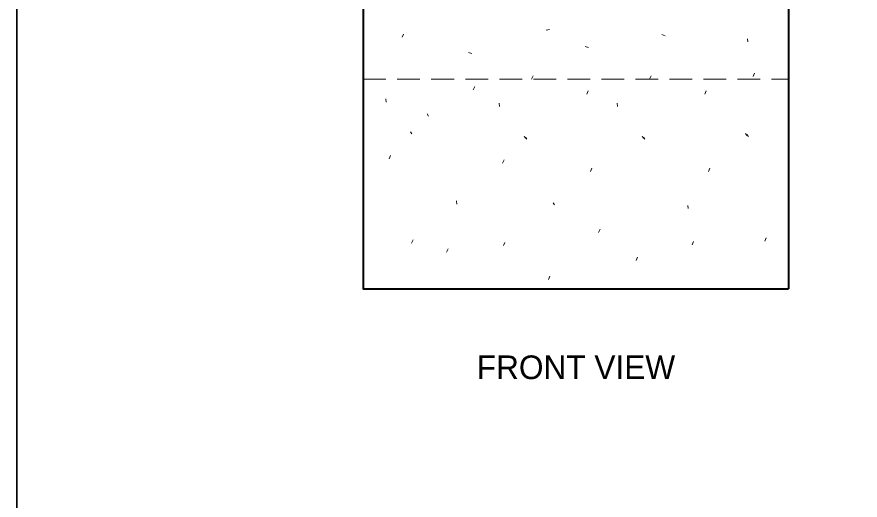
# Model space of a CAD drawing. Extents: x 99860 to 103153, y 99998 to 102077.
# Drawn here: x 99862 to 100576, y 101138 to 101547 of the extents above; entities that cross this region are included whole.
import ezdxf
from ezdxf.enums import TextEntityAlignment as Align

# ---------------------------------------------------------------- set-up
doc = ezdxf.new("R2010")
doc.units = 0
doc.header["$LTSCALE"] = 6.4
doc.linetypes.add('MEDIUM_DASHED', pattern=[4.5, 3, -1.5])
for name, color, linetype, lineweight in [('1', 7, 'Continuous', 13), ('20', 7, 'Continuous', 13), ('7', 7, 'Continuous', 13)]:
    doc.layers.add(name, color=color, linetype=linetype, lineweight=lineweight)

msp = doc.modelspace()

# ---------------------------------------------------------------- linework, layer by layer
at = {"layer": '1', "lineweight": 35}
msp.add_lwpolyline([(99862, 99999.5), (103151, 99999.5), (103151, 102075.5), (99862, 102075.5)], close=True, dxfattribs=at)
at = {"layer": '7', "lineweight": 40}
msp.add_line((100515.171, 101556.572), (100515.171, 101316.572), dxfattribs=at)
at = {"layer": '7'}
for p, q in [((100312.661, 101536.054), (100309.942, 101535.425)), ((100188.029, 101529.482), (100189.279, 101532.252)), ((100407.735, 101531.7), (100410.61, 101530.757)), ((100480.396, 101528.277), (100480.746, 101525.517)), ((100342.974, 101521.73), (100345.86, 101520.778)), ((100244.288, 101516.744), (100247.163, 101515.801)), ((100485.041, 101496.352), (100486.291, 101499.122)), ((100297.621, 101494.062), (100298.861, 101496.832)), ((100397.451, 101494.062), (100398.701, 101496.832)), ((100248.291, 101485.142), (100249.541, 101487.912)), ((100174.201, 101477.462), (100174.541, 101474.692)), ((100344.321, 101481.412), (100345.561, 101484.172)), ((100444.151, 101481.412), (100445.401, 101484.172)), ((100270.221, 101473.732), (100270.571, 101470.962)), ((100370.061, 101473.732), (100370.401, 101470.962)), ((100209.15, 101464.689), (100210.4, 101462.889)), ((100195.231, 101449.512), (100196.401, 101447.712)), ((100291.251, 101445.782), (100292.431, 101443.982)), ((100292.431, 101445.082), (100293.671, 101443.282)), ((100391.091, 101445.782), (100392.261, 101443.982)), ((100392.261, 101445.082), (100393.511, 101443.282)), ((100478.681, 101448.062), (100479.851, 101446.262)), ((100479.851, 101447.372), (100481.101, 101445.572)), ((100177.031, 101426.752), (100178.281, 101429.522)), ((100273.061, 101423.022), (100274.301, 101425.782)), ((100347.431, 101415.962), (100348.671, 101418.722)), ((100447.261, 101415.962), (100448.511, 101418.722)), ((100233.971, 101391.052), (100234.321, 101388.282)), ((100315.756, 101389.57), (100316.926, 101387.77)), ((100429.831, 101387.322), (100430.181, 101384.552)), ((100354.351, 101364.412), (100355.591, 101367.182)), ((100196.121, 101355.422), (100197.371, 101358.192)), ((100273.751, 101353.212), (100274.991, 101355.982)), ((100433.501, 101353.972), (100434.741, 101356.732)), ((100494.931, 101356.942), (100496.181, 101359.712)), ((100225.705, 101347.646), (100226.945, 101350.406)), ((100386.093, 101340.629), (100387.333, 101343.389)), ((100311.913, 101324.591), (100313.153, 101327.351))]:
    msp.add_line(p, q, dxfattribs=at)
at = {"layer": '7', "linetype": 'MEDIUM_DASHED'}
msp.add_line((100155.171, 101494.11), (100515.171, 101494.11), dxfattribs=at)
at = {"layer": '7', "lineweight": 40}
msp.add_lwpolyline([(100155.171, 101556.572), (100155.171, 101316.572), (100515.171, 101316.572)], dxfattribs=at)

# ---------------------------------------------------------------- texts
at = {"layer": '20'}
msp.add_text('FRONT VIEW', height=20, dxfattribs=at).set_placement((100335.177, 101240.326), align=Align.CENTER)

doc.saveas('drawing.dxf')
